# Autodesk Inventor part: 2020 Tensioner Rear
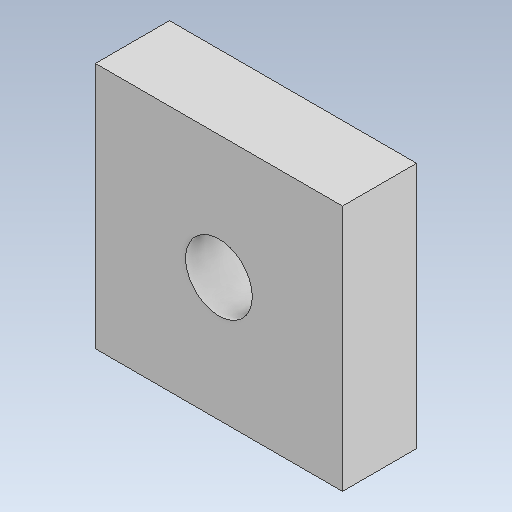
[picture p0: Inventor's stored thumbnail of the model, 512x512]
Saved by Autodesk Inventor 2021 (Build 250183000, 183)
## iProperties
Created: 2023-10
Part Number: 2020 Tensioner Rear
Material: Generico
Document SubType Name: Modeling
Designer: hp
Density: 1 g/cm^3
Appearance: Default
Author: hp
Revision Number: ANY
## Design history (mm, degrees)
feature "Solido1"
body "Solid1"
